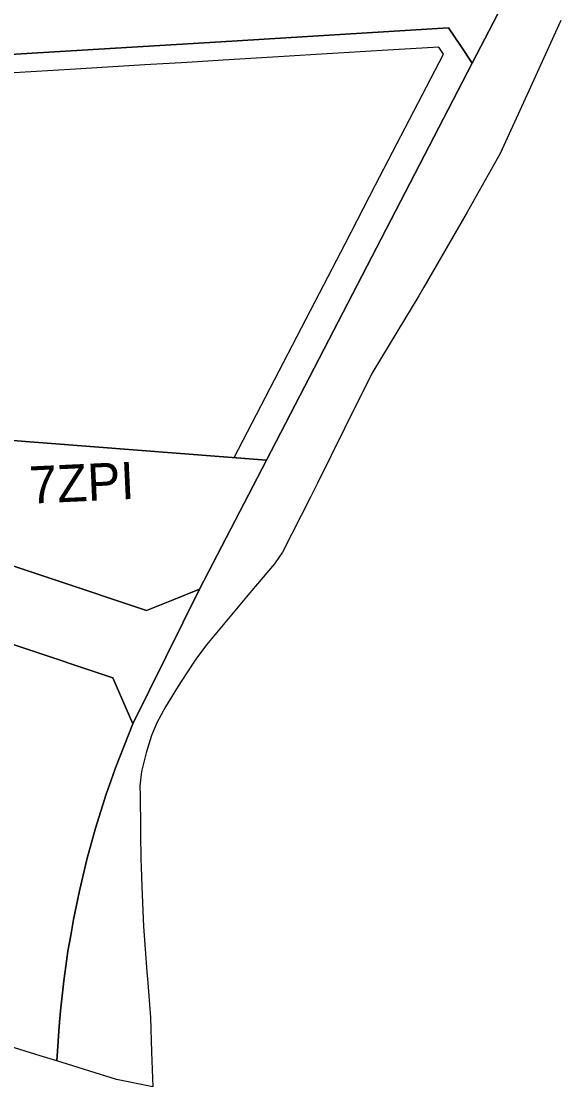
# Model space of a CAD drawing. Extents: x 7418021 to 7419743, y 5540231 to 5541685.
# Drawn here: x 7419339.9 to 7419485, y 5540231.5 to 5540517.9 of the extents above; entities that cross this region are included whole.
import ezdxf

# ---------------------------------------------------------------- set-up
doc = ezdxf.new("R2010")
doc.units = 0
for name, color, linetype in [('linie_rozgraniczajace', 7, 'Continuous'), ('linie_zabudowy_nieprzekraczalne', 7, 'Continuous'), ('oznaczenia_przeznaczen', 7, 'Continuous')]:
    doc.layers.add(name, color=color, linetype=linetype)

msp = doc.modelspace()

# ---------------------------------------------------------------- linework, layer by layer
at = {"layer": 'linie_rozgraniczajace'}
for points in [[(7419477.19, 5540537.56), (7419461.14, 5540506.63), (7419457.97, 5540511.38), (7419454.81, 5540516.14), (7419393.57, 5540512.42), (7419332.34, 5540508.71)], [(7419375.24, 5540231.49), (7419365.45, 5540233.46), (7419349.47, 5540238.4), (7419349.62, 5540241.08), (7419349.77, 5540243.77), (7419350.08, 5540247.8), (7419350.4, 5540251.84), (7419350.84, 5540255.88), (7419351.28, 5540259.93), (7419351.85, 5540263.93), (7419352.41, 5540267.94), (7419353.15, 5540272.18), (7419353.89, 5540276.43), (7419354.7, 5540280.3), (7419355.5, 5540284.18), (7419356.51, 5540288.37), (7419357.52, 5540292.57), (7419358.68, 5540296.77), (7419359.84, 5540300.97), (7419361.27, 5540305.53), (7419362.71, 5540310.09), (7419363.96, 5540313.67), (7419365.21, 5540317.24), (7419367.56, 5540323.16), (7419369.9, 5540329.08), (7419387.79, 5540365.27), (7419405.78, 5540399.94), (7419461.14, 5540506.63), (7419477.19, 5540537.56)], [(7419484.95, 5540518.09), (7419484.45, 5540516.98), (7419476.83, 5540500.23), (7419468.71, 5540482.37), (7419459.77, 5540466.59), (7419448.18, 5540446.45), (7419446.79, 5540444.14), (7419441.15, 5540434.83), (7419434.12, 5540423.22), (7419426.82, 5540408.46), (7419419.53, 5540393.71), (7419417.63, 5540389.98), (7419410.09, 5540375.22), (7419408.16, 5540372.37), (7419407.96, 5540372.07), (7419401.38, 5540364.25), (7419395.52, 5540357.27), (7419389.65, 5540350.3), (7419386.81, 5540346.42), (7419384.42, 5540342.78), (7419382.04, 5540339.14), (7419380.33, 5540336.36), (7419378.62, 5540333.58), (7419376.34, 5540329.32), (7419374.9, 5540325.9), (7419374.16, 5540323.6), (7419373.43, 5540321.29), (7419372.22, 5540316.22), (7419371.76, 5540312.35), (7419371.8, 5540309.72), (7419371.93, 5540301.12), (7419371.95, 5540299.64), (7419372.06, 5540292.52), (7419372.12, 5540290.69), (7419372.33, 5540285.23), (7419372.7, 5540274.6), (7419373.66, 5540262.36), (7419373.89, 5540259.38), (7419374.62, 5540250.11), (7419374.93, 5540240.8), (7419375.24, 5540231.49)], [(7419332.34, 5540508.71), (7419393.57, 5540512.42), (7419454.81, 5540516.14), (7419457.97, 5540511.38), (7419461.14, 5540506.63), (7419405.78, 5540399.94), (7419358.35, 5540403.61), (7419310.92, 5540407.28)], [(7419322.56, 5540376.53), (7419373.53, 5540359.49), (7419380.68, 5540362.41), (7419387.79, 5540365.27), (7419369.9, 5540329.08), (7419367.17, 5540335.26), (7419364.45, 5540341.44), (7419314.85, 5540358.02)], [(7419314.85, 5540358.02), (7419364.45, 5540341.44), (7419367.17, 5540335.26), (7419369.9, 5540329.08), (7419367.56, 5540323.16), (7419365.21, 5540317.24), (7419363.96, 5540313.67), (7419362.71, 5540310.09), (7419361.27, 5540305.53), (7419359.84, 5540300.97), (7419358.68, 5540296.77), (7419357.52, 5540292.57), (7419356.51, 5540288.37), (7419355.5, 5540284.18), (7419354.7, 5540280.3), (7419353.89, 5540276.43), (7419353.15, 5540272.18), (7419352.41, 5540267.94)], [(7419352.41, 5540267.94), (7419351.85, 5540263.93), (7419351.28, 5540259.93), (7419350.84, 5540255.88), (7419350.4, 5540251.84), (7419350.08, 5540247.8), (7419349.77, 5540243.77), (7419349.62, 5540241.08), (7419349.47, 5540238.4), (7419344.96, 5540239.8), (7419321.54, 5540247.04), (7419298.12, 5540254.28), (7419230.79, 5540275.11), (7419173.94, 5540293.61)]]:
    msp.add_lwpolyline(points, dxfattribs=at)
msp.add_lwpolyline([(7419273.82, 5540392.82), (7419289.73, 5540394.72), (7419294.26, 5540396.72), (7419298.78, 5540398.73), (7419302.65, 5540400.69), (7419306.78, 5540403.98), (7419310.92, 5540407.28), (7419358.35, 5540403.61), (7419405.78, 5540399.94), (7419387.79, 5540365.27), (7419380.68, 5540362.41), (7419373.53, 5540359.49), (7419322.56, 5540376.53)], close=True, dxfattribs=at)
at = {"layer": 'linie_zabudowy_nieprzekraczalne'}
for points in [[(7419419.21, 5540508.97), (7419407.51, 5540508.26)], [(7419436.92, 5540510.05), (7419419.21, 5540508.97)], [(7419435.16, 5540473.93), (7419453.42, 5540509.11)], [(7419452.21, 5540510.98), (7419436.92, 5540510.05)], [(7419453.42, 5540509.11), (7419452.21, 5540510.98)], [(7419373.06, 5540506.17), (7419354.41, 5540505.04)], [(7419384.49, 5540506.86), (7419373.06, 5540506.17)], [(7419394.17, 5540507.45), (7419384.49, 5540506.86)], [(7419407.51, 5540508.26), (7419394.17, 5540507.45)], [(7419354.41, 5540505.04), (7419336.43, 5540503.95)], [(7419426.94, 5540458.08), (7419435.16, 5540473.93)], [(7419420.05, 5540444.8), (7419426.94, 5540458.08)], [(7419397.12, 5540400.61), (7419420.05, 5540444.8)]]:
    msp.add_lwpolyline(points, dxfattribs=at)

# ---------------------------------------------------------------- texts
at = {"layer": 'oznaczenia_przeznaczen'}
msp.add_text('7ZPI', height=10, rotation=2.669, dxfattribs=at).set_placement((7419342.25, 5540388.22))

doc.saveas('drawing.dxf')
